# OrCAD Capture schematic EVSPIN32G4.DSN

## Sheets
1 PAGE1 - STSPIN32G4: size A4; rev: 1
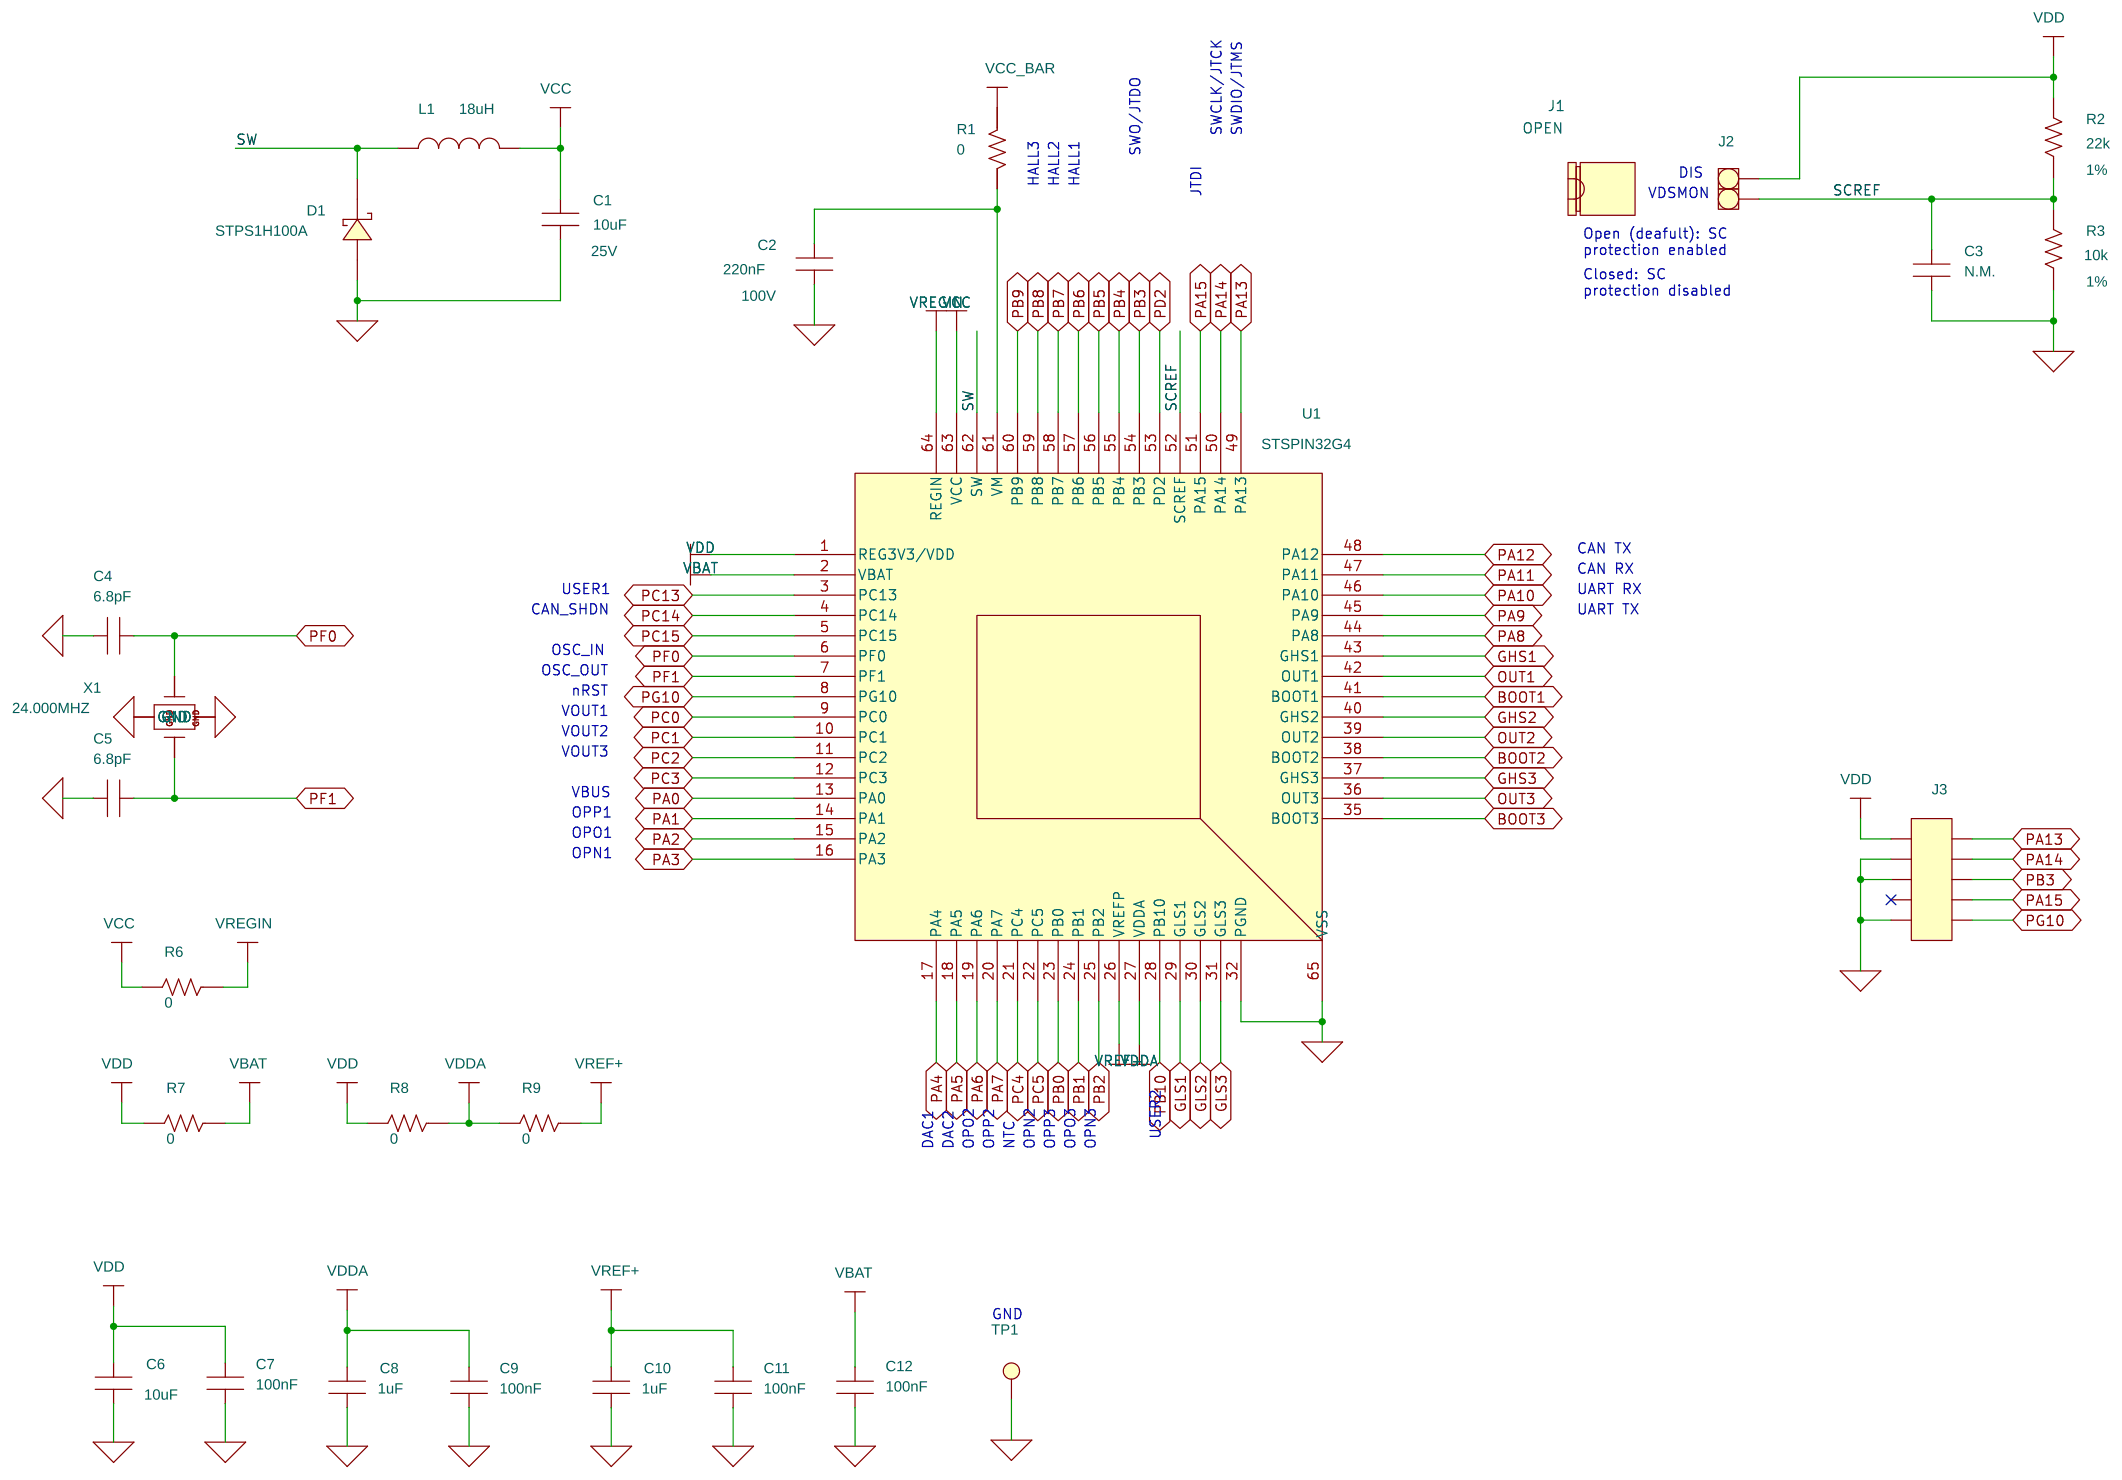
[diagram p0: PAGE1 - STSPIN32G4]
2 PAGE2 - Power Stage: size A4
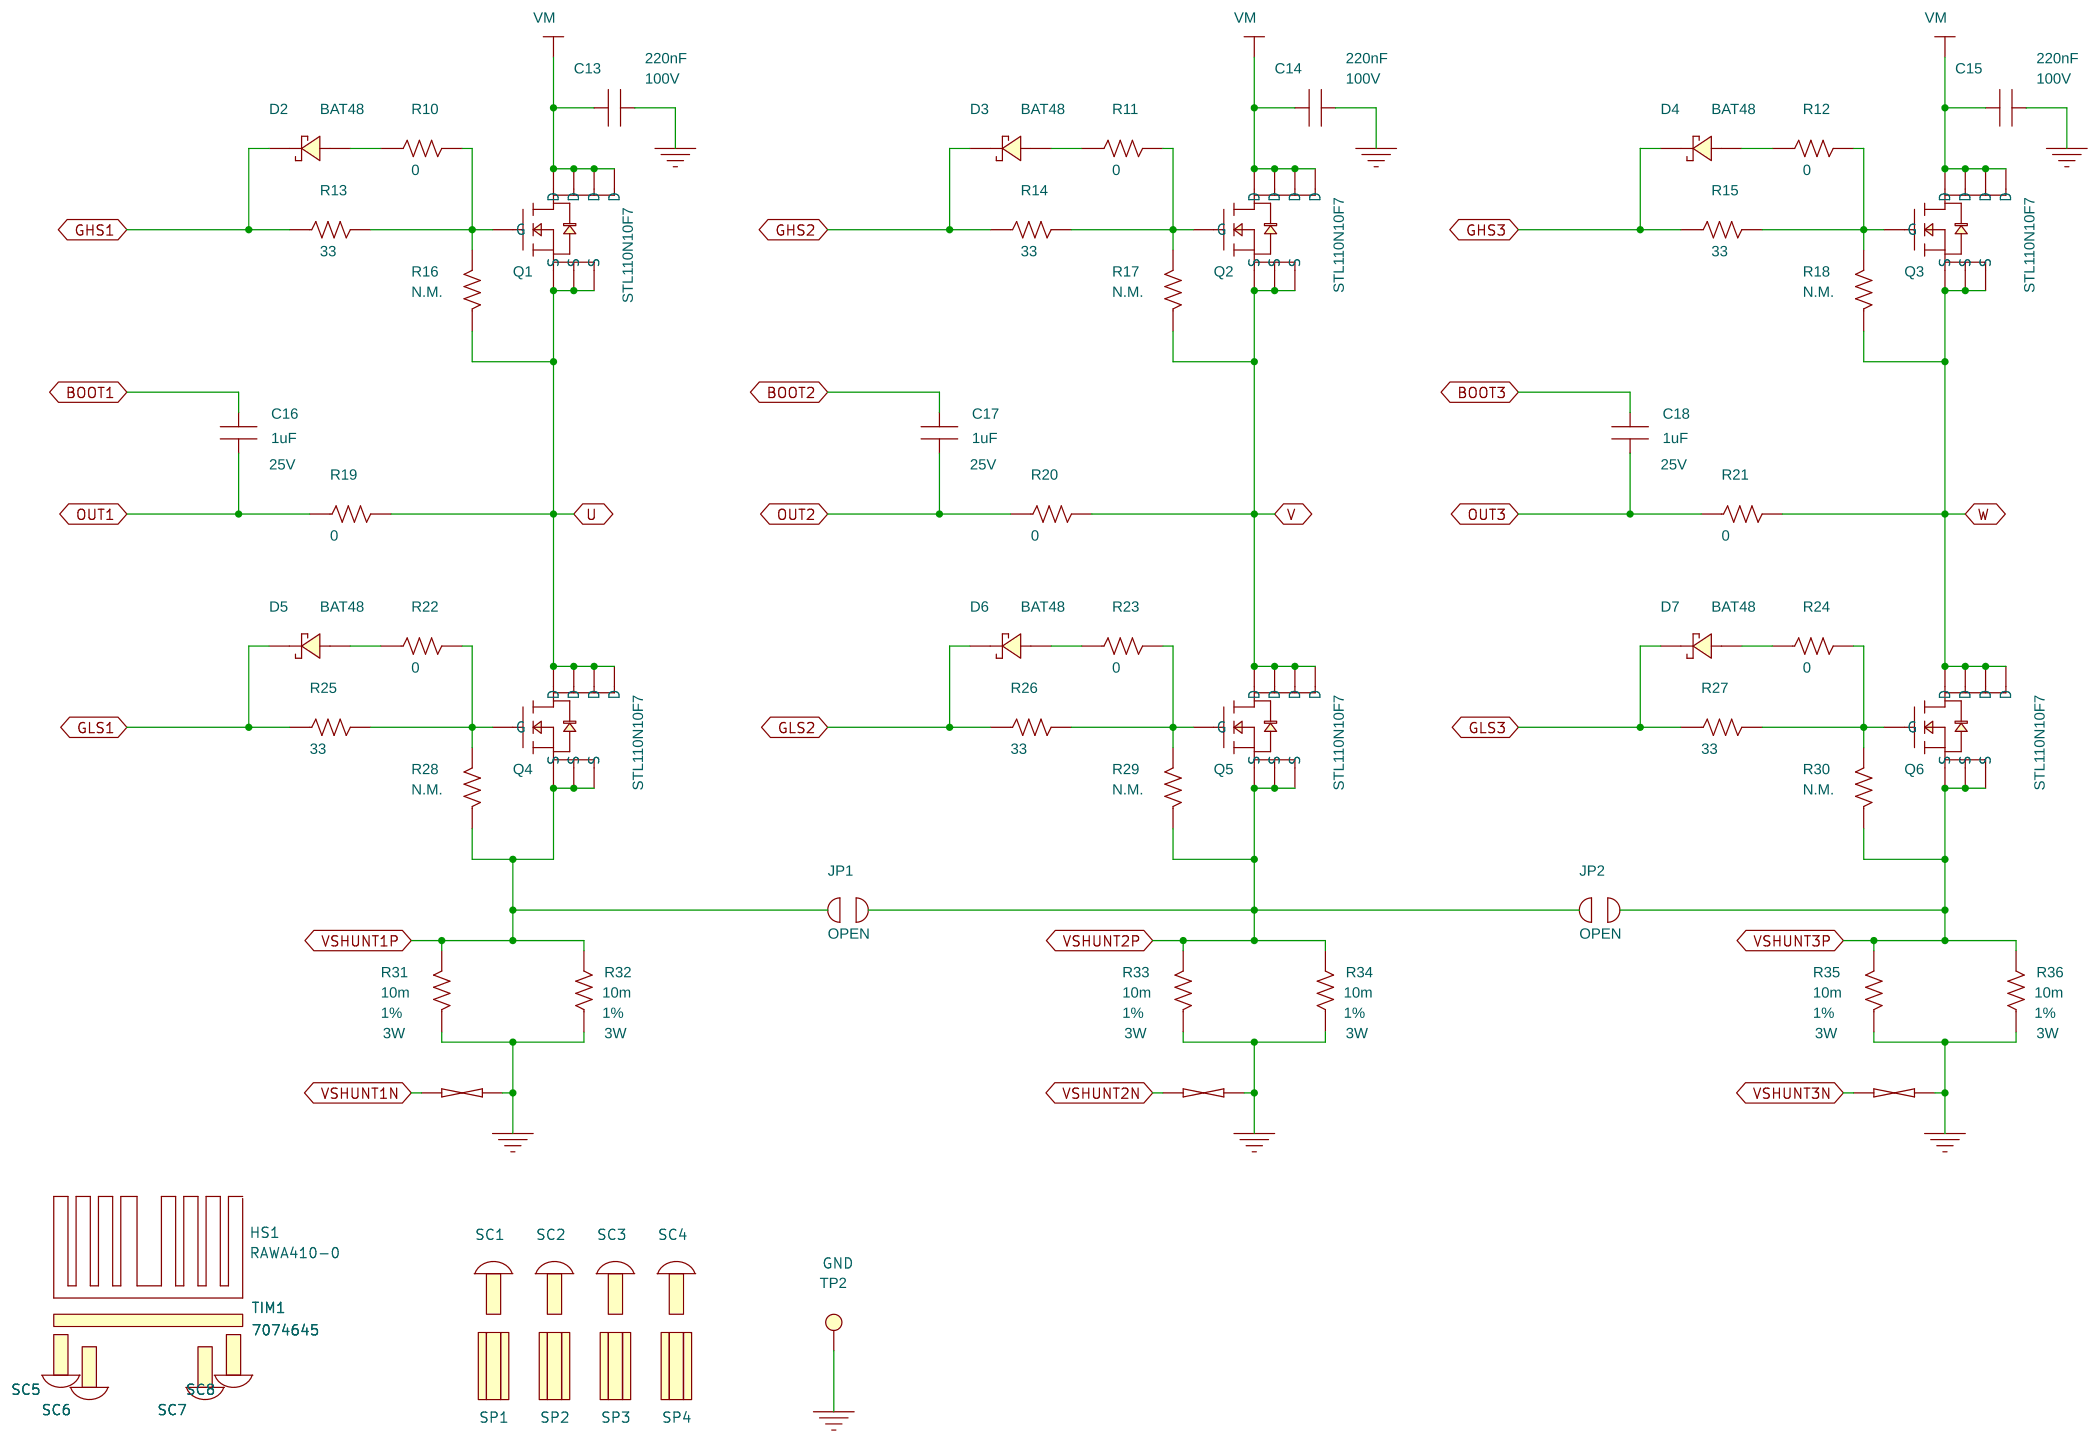
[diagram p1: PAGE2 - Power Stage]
3 PAGE3 - Analog Sensing: size A4
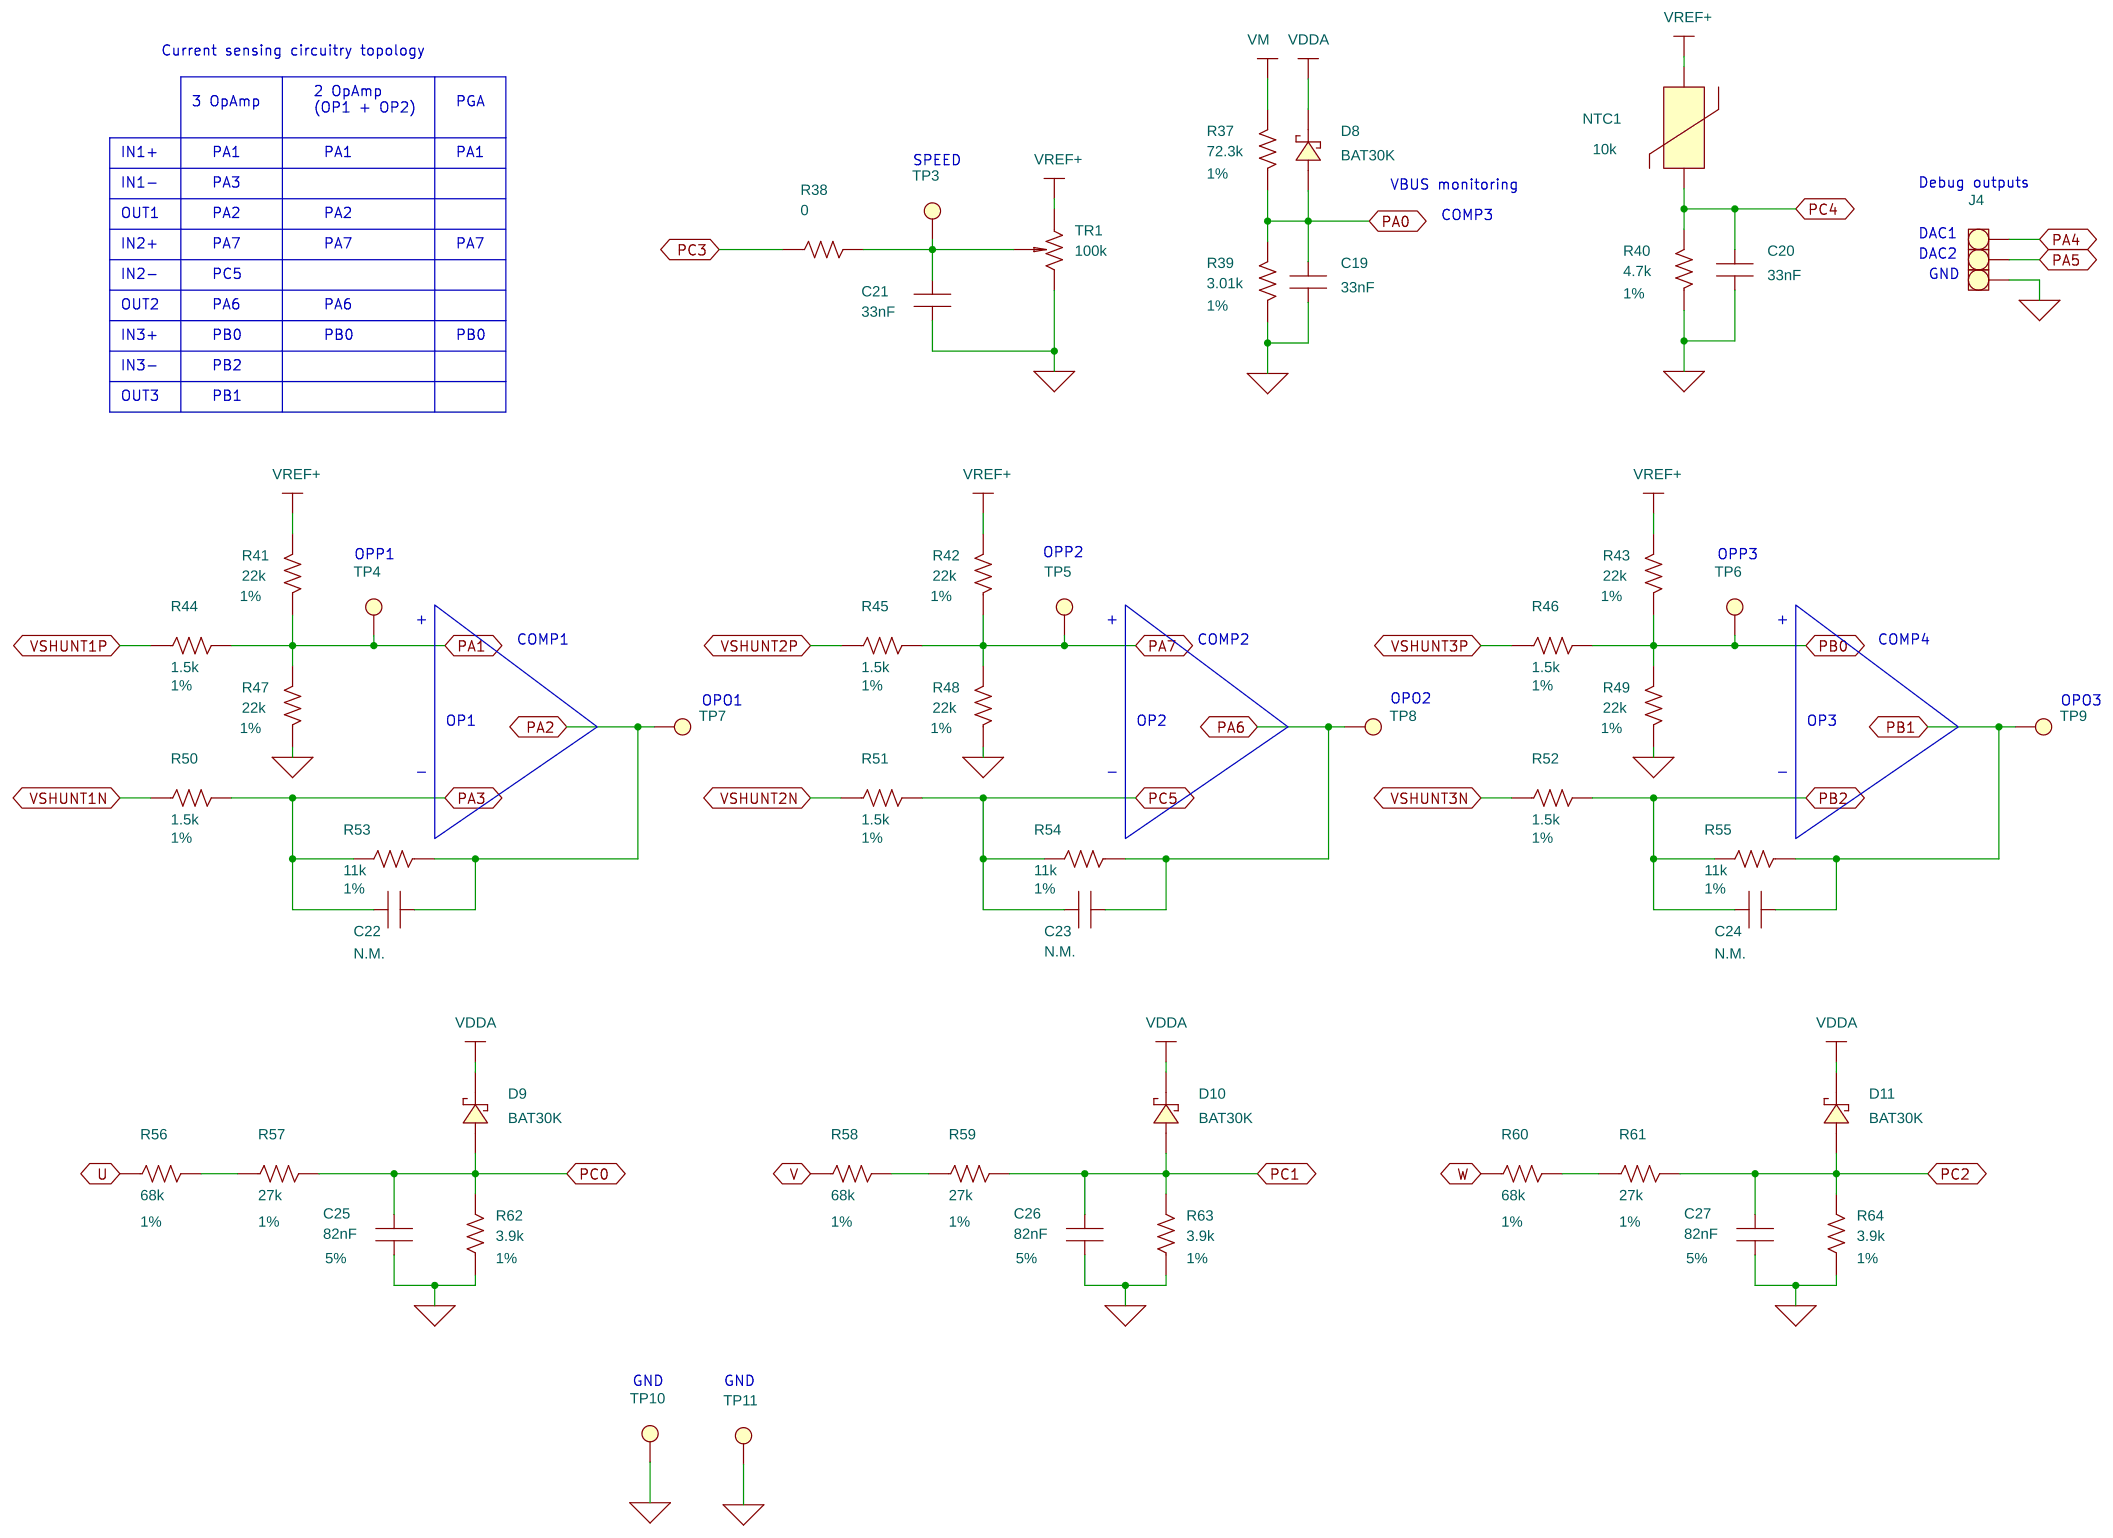
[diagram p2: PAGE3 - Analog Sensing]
4 PAGE4 - Arduino connector: size A4
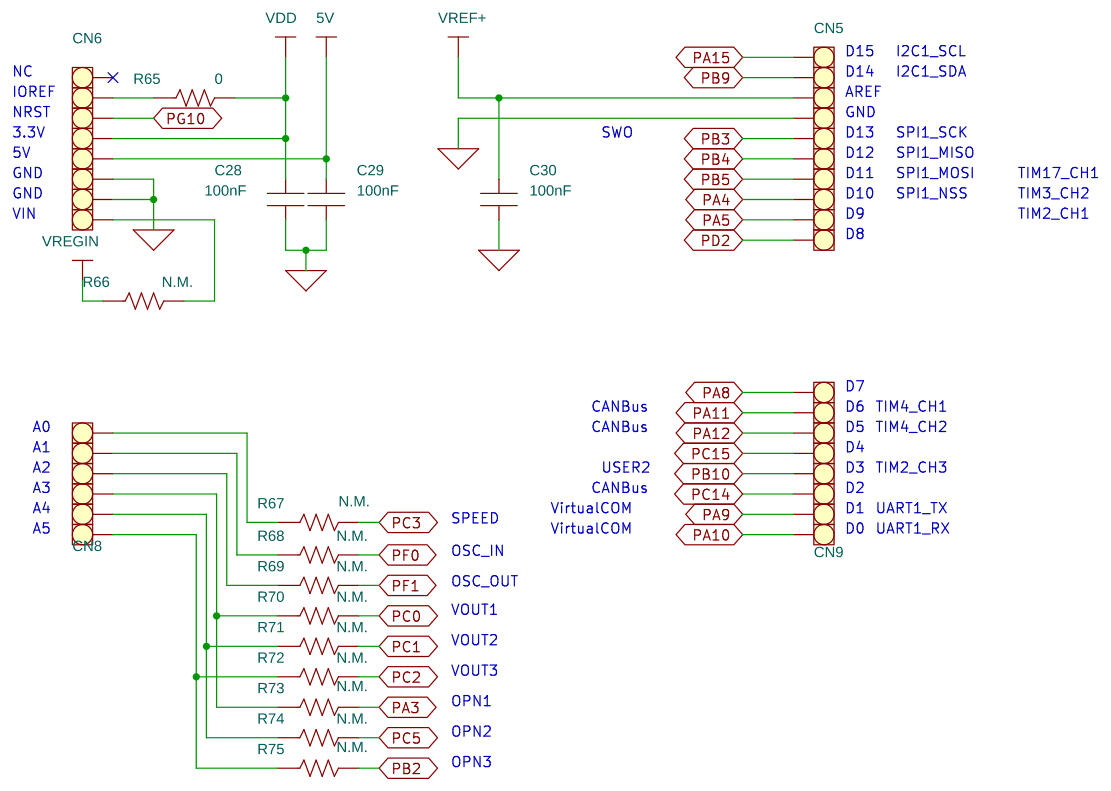
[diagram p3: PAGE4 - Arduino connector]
5 PAGE5 - Inputs and Outputs: size A4
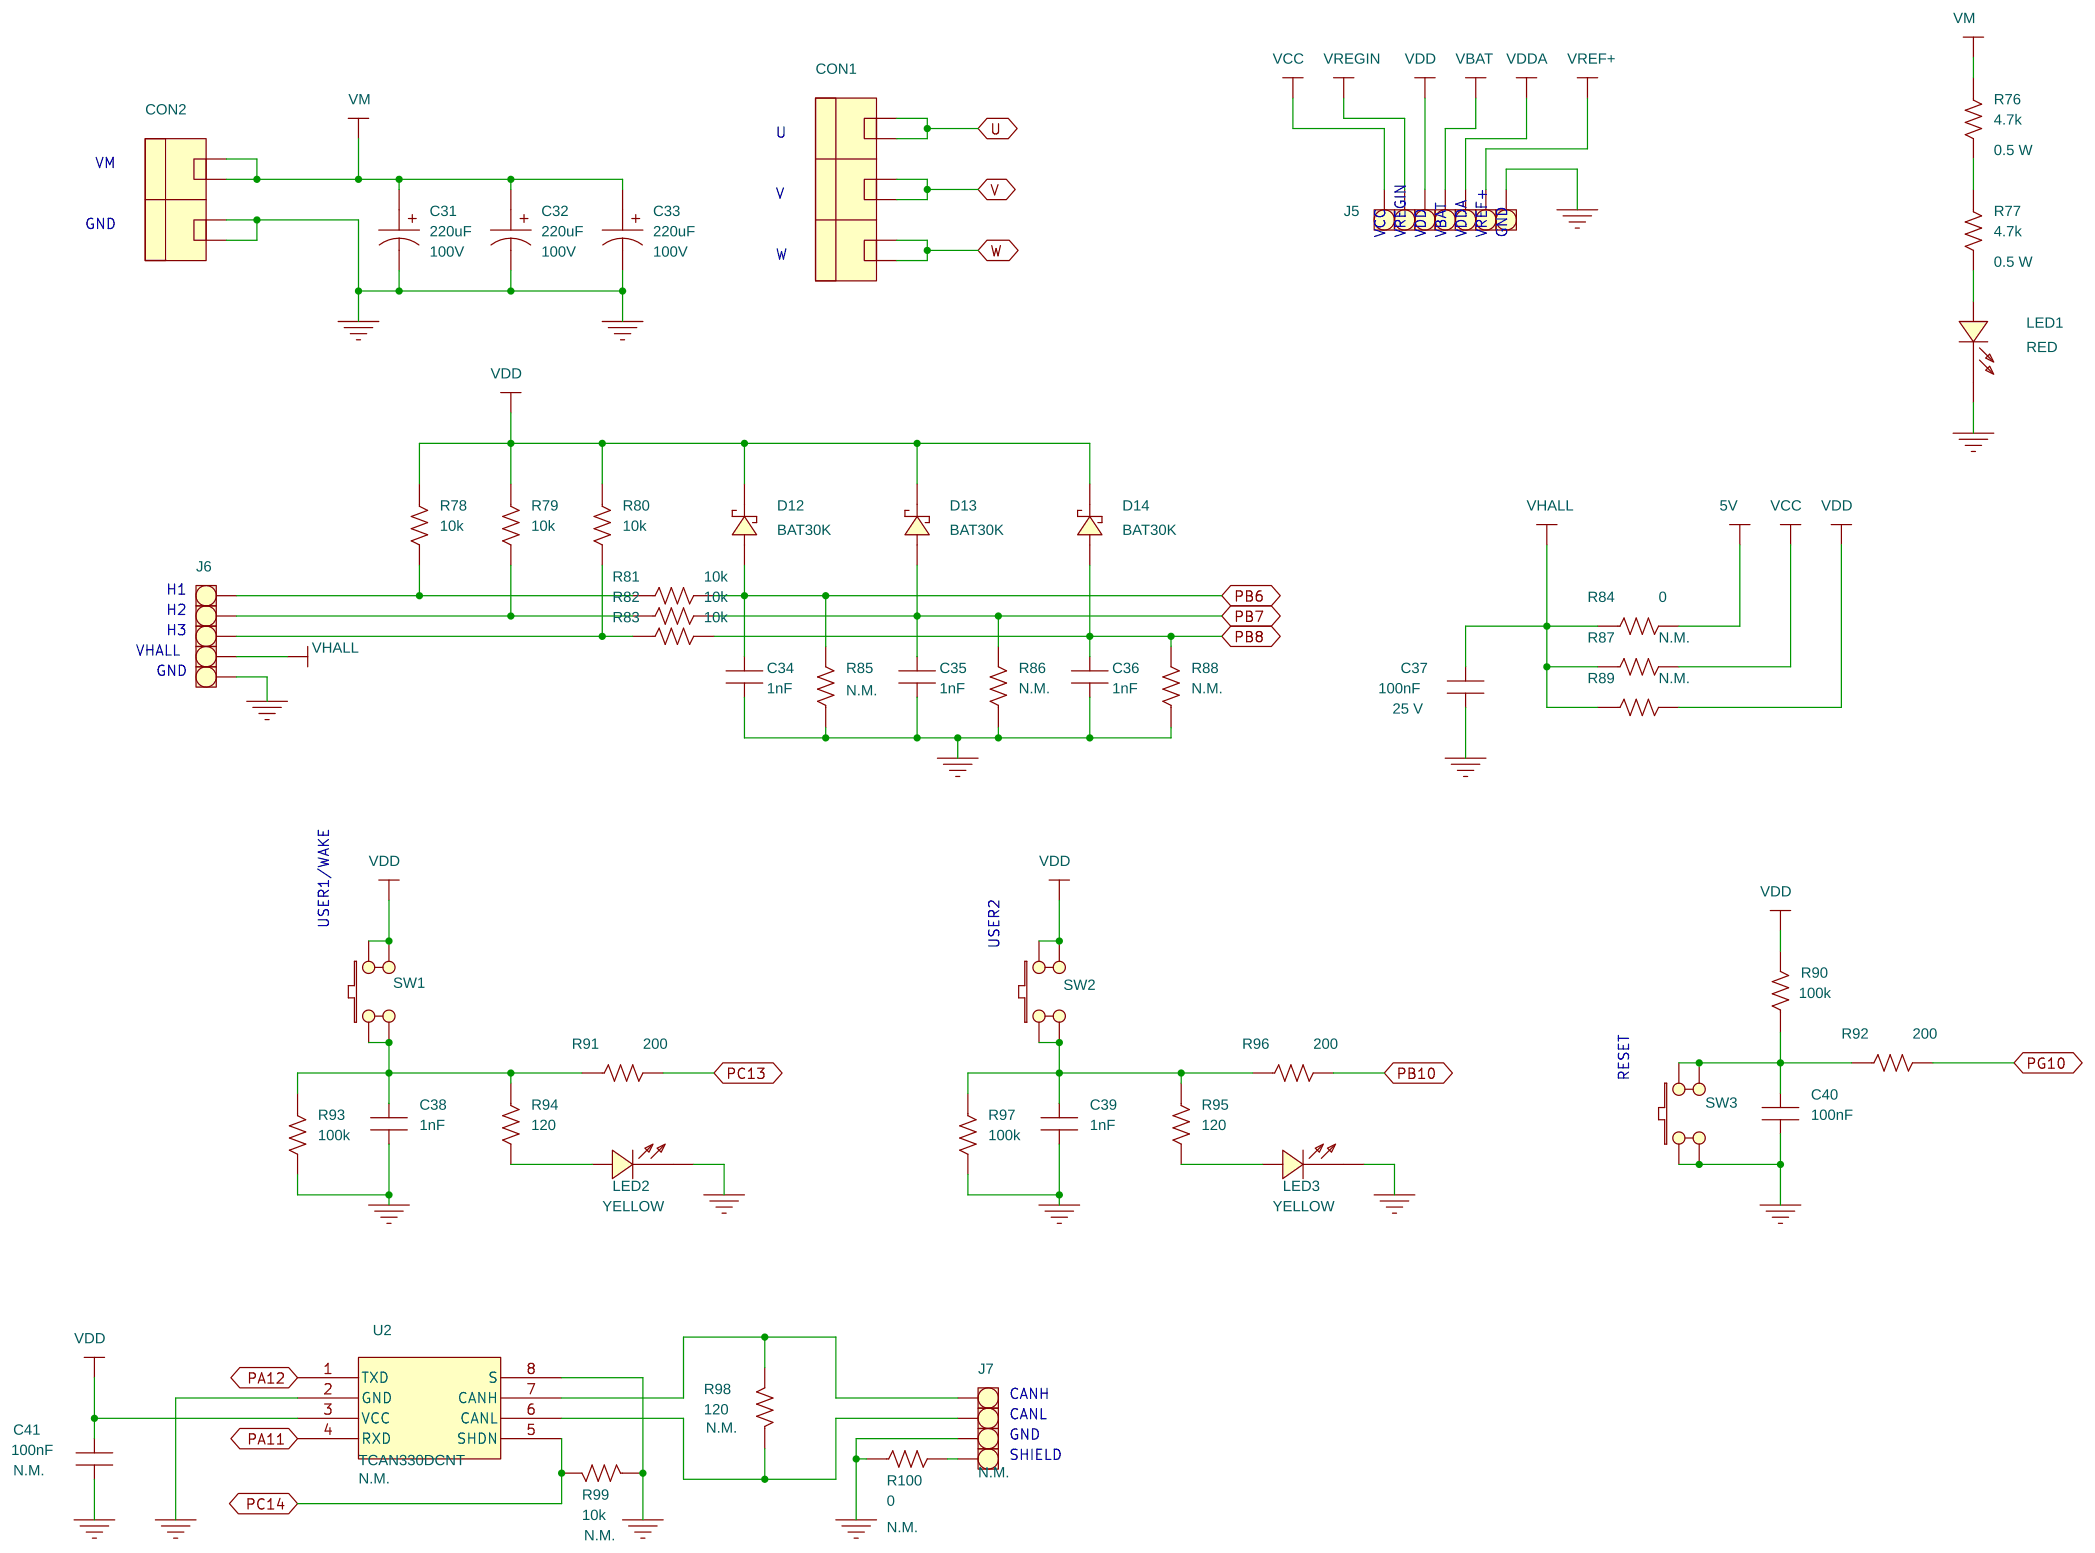
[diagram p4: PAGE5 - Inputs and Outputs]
6 PAGE6 - STLINK: size A4
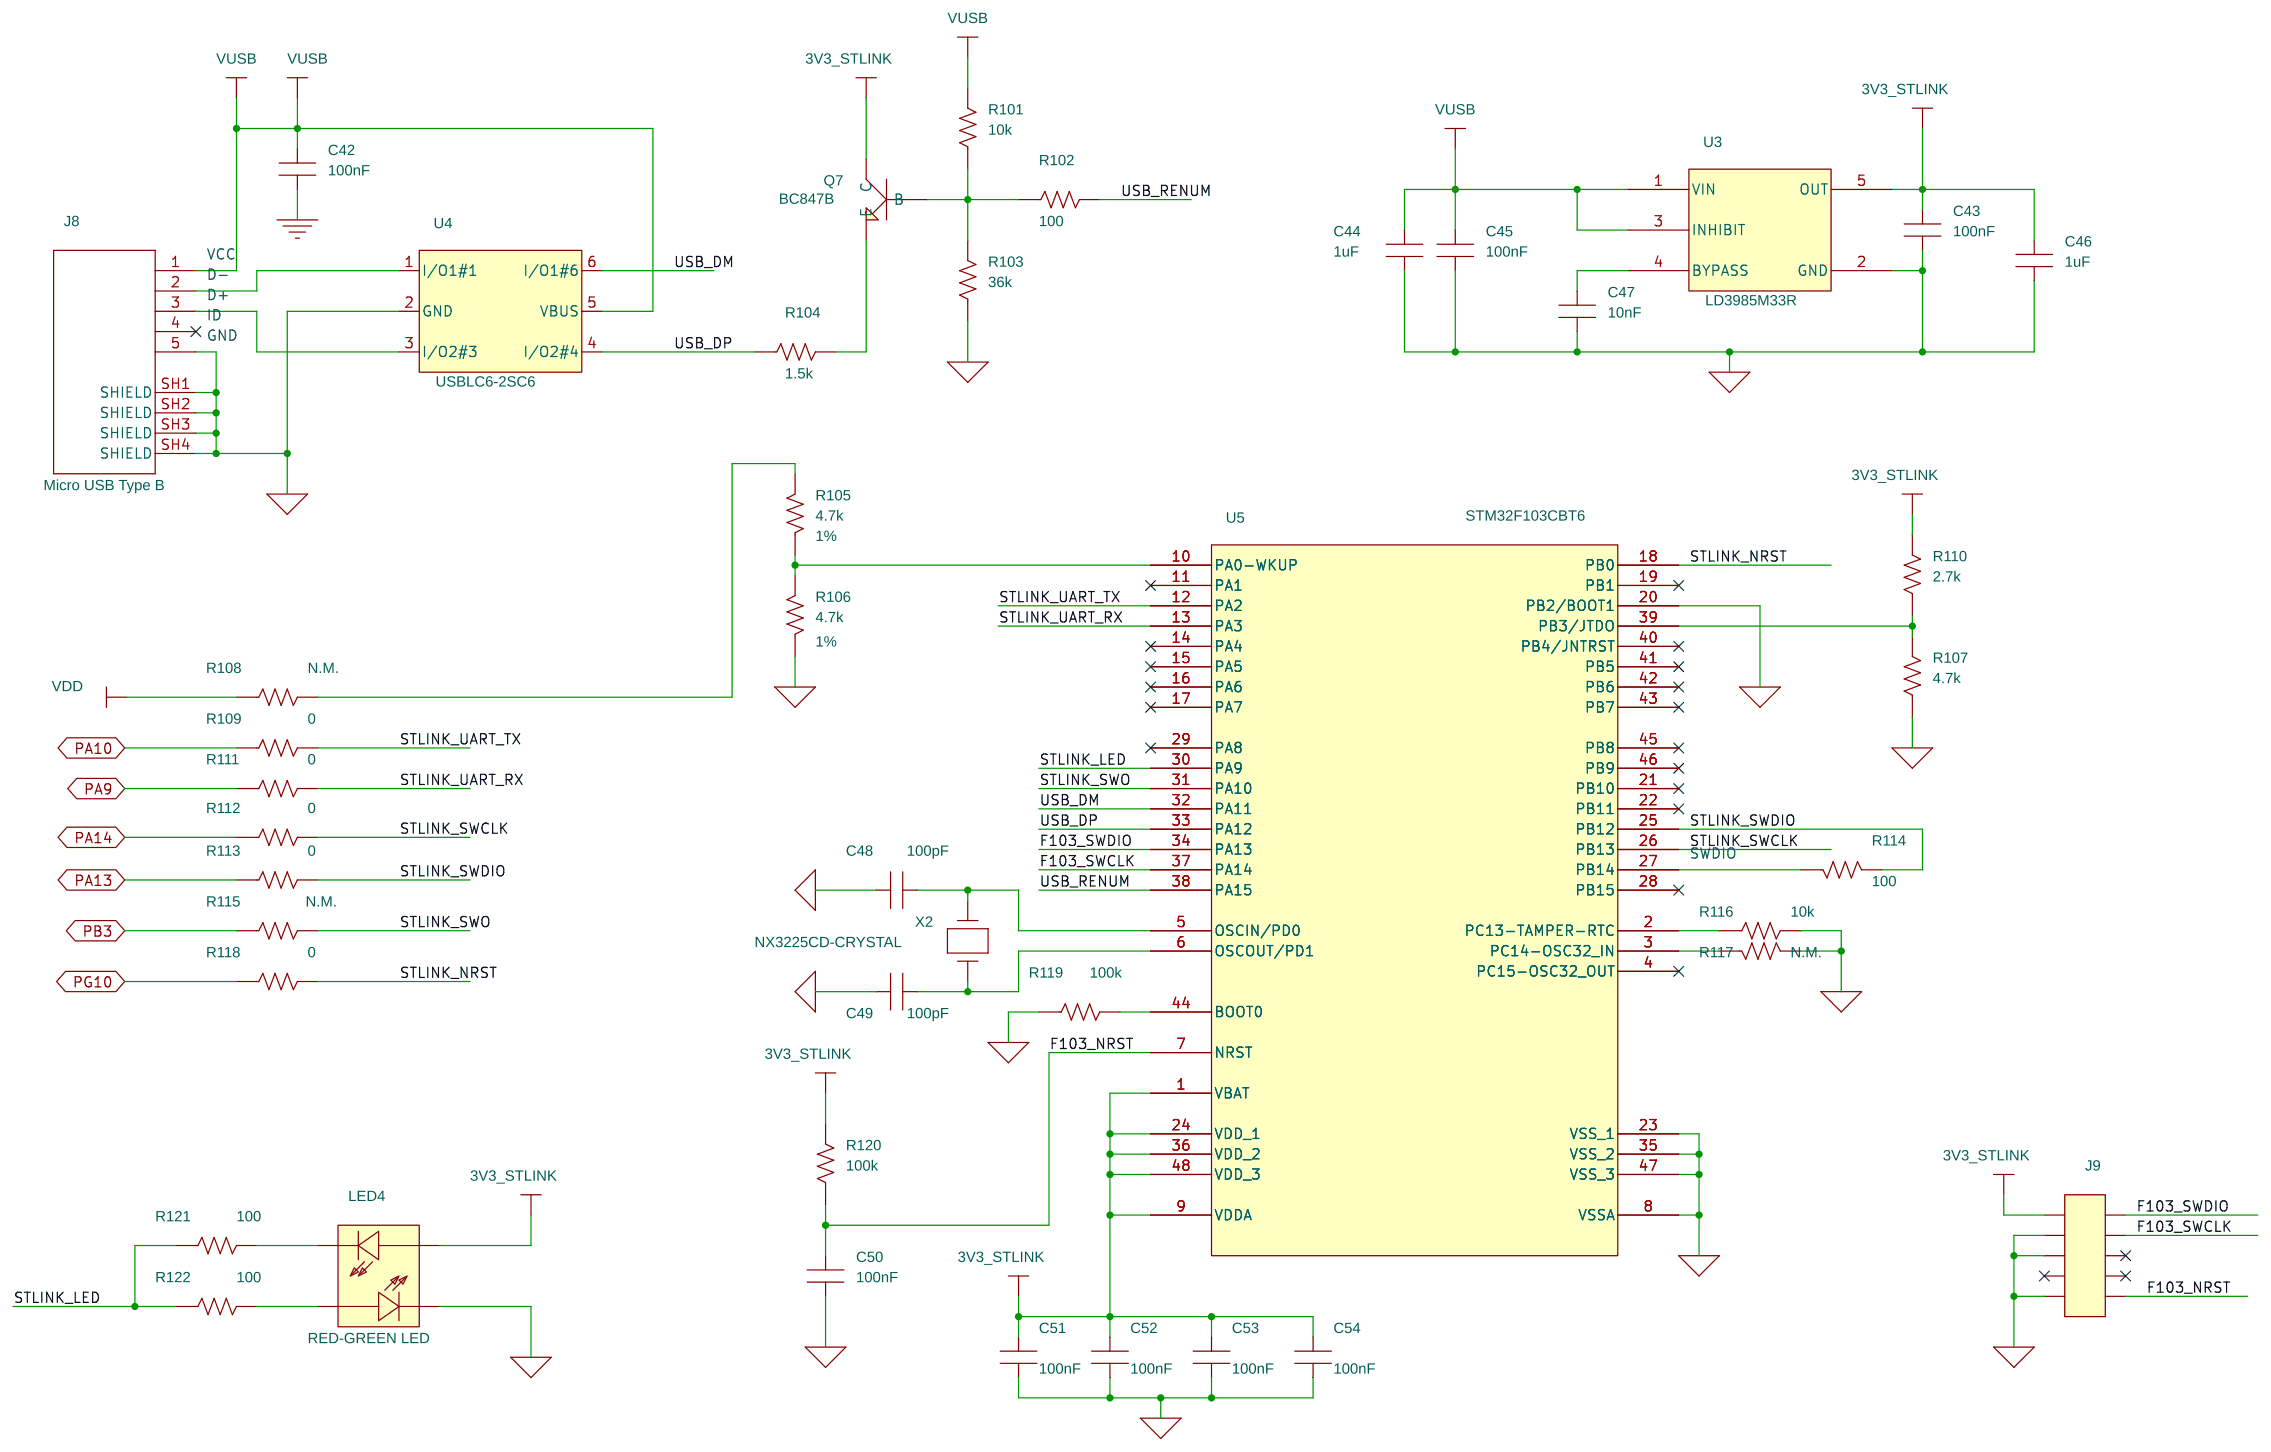
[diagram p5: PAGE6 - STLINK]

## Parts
sheet PAGE1 - STSPIN32G4
C1  10uF  [C0805]
C2  220nF  [C0805]
C3  C-0603  [C0603]
C4  6.8pF  [C0402]
C5  6.8pF  [C0402]
C6  10uF  [C0805]
C7  100nF  [C0603]
C8  1uF  [C0603]
C9  100nF  [C0603]
C10  1uF  [C0603]
C11  100nF  [C0603]
C12  100nF  [C0603]
D1  STPS1H100A  [SMA]
J1  OPEN
J2  STRIP 1x2  [STRIP254P-M-2]
J3  STRIP 2x5  [PIN2X5P127]
L1  18uH  [7447732115-WURTH]
R1  0  [J0805]
R2  22k  [R0603]
R3  10k  [R0603]
R6  0  [J0805]
R7  0  [J0805]
R8  0  [J0805]
R9  0  [J0805]
TP1  TP-SMD-S1751-46R  [tp_SMD_135_70]
U1  STSPIN32G4  [VFQFPN9x9x1_0-64L-EXP]
X1  24.000MHZ  [ABMM11W]
sheet PAGE2 - Power Stage
C13  220nF  [C0805]
C14  220nF  [C0805]
C15  220nF  [C0805]
C16  1uF  [C0805]
C17  1uF  [C0805]
C18  1uF  [C0805]
D2  BAT48  [SOD-323]
D3  BAT48  [SOD-323]
D4  BAT48  [SOD-323]
D5  BAT48  [SOD-323]
D6  BAT48  [SOD-323]
D7  BAT48  [SOD-323]
HS1  RAWA410-0
JP1  OPEN  [JUMPER-LARGO5_5MM]
JP2  OPEN  [JUMPER-LARGO5_5MM]
NET1  PCB short  [CurrentSense]
NET2  PCB short  [CurrentSense]
NET3  PCB short  [CurrentSense]
Q1  STL110N10F7  [PFLAT_6X5-8LEADS]
Q2  STL110N10F7  [PFLAT_6X5-8LEADS]
Q3  STL110N10F7  [PFLAT_6X5-8LEADS]
Q4  STL110N10F7  [PFLAT_6X5-8LEADS]
Q5  STL110N10F7  [PFLAT_6X5-8LEADS]
Q6  STL110N10F7  [PFLAT_6X5-8LEADS]
R10  0  [R0603]
R11  0  [R0603]
R12  0  [R0603]
R13  33  [R0603]
R14  33  [R0603]
R15  33  [R0603]
R16  R-0805  [R0603]
R17  R-0805  [R0603]
R18  R-0805  [R0603]
R19  0  [R0603]
R20  0  [R0603]
R21  0  [R0603]
R22  0  [R0603]
R23  0  [R0603]
R24  0  [R0603]
R25  33  [R0603]
R26  33  [R0603]
R27  33  [R0603]
R28  R-0805  [R0603]
R29  R-0805  [R0603]
R30  R-0805  [R0603]
R31  10m  [R2512]
R32  10m  [R2512]
R33  10m  [R2512]
R34  10m  [R2512]
R35  10m  [R2512]
R36  10m  [R2512]
SC1  M3
SC2  M3
SC3  M3
SC4  M3
SC5  M3
SC6  M3
SC7  M3
SC8  M3
SP1  222424
SP2  222424
SP3  222424
SP4  222424
TIM1  7074645
TP2  TP-SMD-S1751-46R  [tp_SMD_135_70]
sheet PAGE3 - Analog Sensing
C19  33nF  [C0603]
C20  33nF  [C0603]
C21  33nF  [C0603]
C22  C-0603  [C0603]
C23  C-0603  [C0603]
C24  C-0603  [C0603]
C25  82nF  [C0603]
C26  82nF  [C0603]
C27  82nF  [C0603]
D8  BAT30K  [SOD523]
D9  BAT30K  [SOD523]
D10  BAT30K  [SOD523]
D11  BAT30K  [SOD523]
J4  STRIP 1x3  [STRIP254P-M-3]
NTC1  10k  [R0603]
R37  72.3k  [R0603]
R38  0  [J0805]
R39  3.01k  [R0603]
R40  4.7k  [R0603]
R41  22k  [R0603]
R42  22k  [R0603]
R43  22k  [R0603]
R44  1.5k  [R0603]
R45  1.5k  [R0603]
R46  1.5k  [R0603]
R47  22k  [R0603]
R48  22k  [R0603]
R49  22k  [R0603]
R50  1.5k  [R0603]
R51  1.5k  [R0603]
R52  1.5k  [R0603]
R53  11k  [R0603]
R54  11k  [R0603]
R55  11k  [R0603]
R56  68k  [R0603]
R57  27k  [R0603]
R58  68k  [R0603]
R59  27k  [R0603]
R60  68k  [R0603]
R61  27k  [R0603]
R62  3.9k  [R0603]
R63  3.9k  [R0603]
R64  3.9k  [R0603]
TP3  TP-SMD-diam1_5mm  [TP-D60]
TP4  TP-SMD-diam1_5mm  [TP-D60]
TP5  TP-SMD-diam1_5mm  [TP-D60]
TP6  TP-SMD-diam1_5mm  [TP-D60]
TP7  TP-SMD-diam1_5mm  [TP-D60]
TP8  TP-SMD-diam1_5mm  [TP-D60]
TP9  TP-SMD-diam1_5mm  [TP-D60]
TP10  TP-diam1_27mm-Hole0_8mm  [TP-SONDA]
TP11  TP-diam1_27mm-Hole0_8mm  [TP-SONDA]
TR1  100k  [TRIMMER-3386P-BOURNS]
sheet PAGE4 - Arduino connector
C28  100nF  [C0603]
C29  100nF  [C0603]
C30  100nF  [C0603]
CN5  STRIP-P2_54-10P-FEMALE  [SIL-SOCKET10PIN-P254]
CN6  STRIP-P2_54-8P-FEMALE  [SIL-SOCKET8PIN-P254]
CN8  STRIP-P2_54-6P-FEMALE  [SIL-SOCKET6PIN-P254]
CN9  STRIP-P2_54-8P-FEMALE  [SIL-SOCKET8PIN-P254]
R65  0  [J0805]
R66  0  [J0805]
R67  0  [J0805]
R68  0  [J0805]
R69  0  [J0805]
R70  0  [J0805]
R71  0  [J0805]
R72  0  [J0805]
R73  0  [J0805]
R74  0  [J0805]
R75  0  [J0805]
sheet PAGE5 - Inputs and Outputs
C31  220uF  [D500p200]
C32  220uF  [D500p200]
C33  220uF  [D500p200]
C34  1nF  [C0603]
C35  1nF  [C0603]
C36  1nF  [C0603]
C37  100nF  [C0603]
C38  1nF  [C0603]
C39  1nF  [C0603]
C40  100nF  [C0603]
C41  100nF  [C0603]
CON1  Power con3P  [2834082-2-TE]
CON2  Power con2P  [2834082-1-TE]
D12  BAT30K  [SOD523]
D13  BAT30K  [SOD523]
D14  BAT30K  [SOD523]
J5  STRIP 1x7  [STRIP254P-M-7]
J6  STRIP 1x5  [STRIP254P-M-5]
J7  STRIP 1x4  [STRIP254P-M-4]
LED1  RED  [led-0805]
LED2  YELLOW  [led-0603]
LED3  YELLOW  [led-0603]
R76  4.7k  [R0805]
R77  4.7k  [R0805]
R78  10k  [R0603]
R79  10k  [R0603]
R80  10k  [R0603]
R81  10k  [R0603]
R82  10k  [R0603]
R83  10k  [R0603]
R84  0  [J0805]
R85  R-0603  [R0603]
R86  R-0603  [R0603]
R87  0  [J0805]
R88  R-0603  [R0603]
R89  0  [J0805]
R90  100k  [R0603]
R91  200  [R0603]
R92  200  [R0603]
R93  100k  [R0603]
R94  120  [R0603]
R95  120  [R0603]
R96  200  [R0603]
R97  100k  [R0603]
R98  120  [R0603]
R99  10k  [R0603]
R100  0  [J0805]
SW1  6x6 J-bend SMT  [BUTTON_L6_2_W6_2]
SW2  6x6 J-bend SMT  [BUTTON_L6_2_W6_2]
SW3  6x6 J-bend SMT  [BUTTON_L6_2_W6_2]
U2  TCAN330DCNT  [SOT23-8L]
sheet PAGE6 - STLINK
C42  100nF  [C0603]
C43  100nF  [C0603]
C44  1uF  [C0603]
C45  100nF  [C0603]
C46  1uF  [C0603]
C47  10nF  [C0603]
C48  100pF  [C0603]
C49  100pF  [C0603]
C50  100nF  [C0603]
C51  100nF  [C0603]
C52  100nF  [C0603]
C53  100nF  [C0603]
C54  100nF  [C0603]
J8  Micro USB Type B  [629105150521-USB-MICRO-B-WE]
J9  STRIP 2x5  [PIN2X5P127]
LED4  RED-GREEN LED  [PLCC4]
Q7  BC847B  [SOT23]
R101  10k  [R0603]
R102  100  [R0603]
R103  36k  [R0603]
R104  1.5k  [R0603]
R105  4.7k  [R0603]
R106  4.7k  [R0603]
R107  4.7k  [R0603]
R108  0  [J0805]
R109  0  [J0805]
R110  2.7k  [R0603]
R111  0  [J0805]
R112  0  [J0805]
R113  0  [J0805]
R114  100  [R0603]
R115  0  [J0805]
R116  10k  [R0603]
R117  R-0603  [R0603]
R118  0  [J0805]
R119  100k  [R0603]
R120  100k  [R0603]
R121  100  [R0603]
R122  100  [R0603]
U3  LD3985M33R  [SOT23-5L]
U4  USBLC6-2SC6  [SOT23-6L]
U5  STM32F103CBT6  [LQFP48_L7_W7_P0_5]
X2  NX3225CD-CRYSTAL  [XTAL_L3_2_W2_5_2PINS]

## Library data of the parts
C1 = C-0805: TOLERANCE: 10%; VOLTAGE: 25V
C2 C13-C15 = C-0805: TOLERANCE: 10%; VOLTAGE: 100V
C3 C22-C24 C41 = C-0603: Mounting: N.M.; TOLERANCE: 10%; VOLTAGE: 6.3V
C4 C5 = C-0402: TOLERANCE: 0.25pF; VOLTAGE: 6.3V
C6 = C-0805: TOLERANCE: 10%; VOLTAGE: 6.3V
C7 C9 C11 C12 C19-C21 C28-C30 C34-C36 C38-C40 C42 C43 C45 C47-C54 = C-0603: TOLERANCE: 10%; VOLTAGE: 6.3V
C8 C10 C44 C46 = C-0603: Manufacturer: WURTH ELEKTRONIK; Part Number: 885012206076; TOLERANCE: 10%; VOLTAGE: 6.3V
D1 = STPS1H100A: Voltage: 100V
J1 = Jumper: Manufacturer: WURTH ELEKTRONIK; Package: 2.54mm; Part Number: 60900213421 or equivalent
J2 = STRIP_1x2
J3 J9 = STRIP_2x5: Manufacturer: WURTH ELEKTRONIK; Part Number: 62201021121 or FTSH-105-01-F-D-K
L1 = INDUCTOR-7447732115-WE: ISAT: 1A; Manufacturer: WURTH ELEKTRONIK; Part Number: 744045180 or 7447732115
R1 R6-R9 R38 R65 R84 R109 R111-R113 R118 = R-0603: POWER: 0.1W; Package: Size 0805; TOLERANCE: 5%
R2 R3 R37 R39-R64 R105 R106 = R-0603: POWER: 0.1W; TOLERANCE: 1%
TP1 TP2 = TP-SMD-S2761-46R: Part Number: S1751-46R or equivalent
U1 = STSPIN32G4
X1 = CRYSTAL-ABM11W
C16-C18 = C-0805: Manufacturer: WURTH ELEKTRONIK; Part Number: 885012207078; TOLERANCE: 10%; VOLTAGE: 25V
D2-D7 = BAT60J: Part Number: BAT48JFILM or equivalent; VOLTAGE: 40 V
HS1 = HS-501: Heatsink; Manufacturer: SCHAFFNER; Package: 47.5mm x 51.3mm; Part Number: RAWA410-0 or Equivalent
JP1 JP2 = Jumper_a_Goccia-Largo_5_5mm: Mounting: N.M.
NET1-NET3 = CurrentSense: Mounting: N.M.
Q1-Q6 = STLD110N10F7: N-channel 100 V, 5 mO typ., 107 A STripFET F7 Power MOSFET; Package: PowerFLAT 5x6; Part Number: STL110N10F7 or equivalent
R10-R15 R19-R27 = R-0805: POWER: 0.1W; Package: Size 0603; TOLERANCE: 5%
R16-R18 R28-R30 = R-0805: Mounting: N.M.; POWER: 0.1W; Package: Size 0603; TOLERANCE: 5%
R31-R36 = R-2512: Manufacturer: Bourns; POWER: 3W; Part Number: CRA2512-FZ-R010ELF or equivalent; TOLERANCE: 1%
SC1-SC8 = M3: M3 Cheese-head screw; Package: M3x8mm
SP1-SP4 = 222424: M3 F-F Hexagonal spacer 20 mm; Manufacturer: RS-PRO; Part Number: 222-424
TIM1 = 7074645: Thermally conductive Gap filler, 150x150 mm sp.0,5 mm.; Manufacturer: RS-PRO; Package: 47.5mm x 51.3mm; Part Number: 707-4645
C25-C27 = C-0603: TOLERANCE: 5%; VOLTAGE: 6.3V
D8-D14 = BAT30K
J4 = STRIP_1x3: Manufacturer: WURTH ELEKTRONIK; Part Number: 61300311121 or equivalent
NTC1 = NTC-NCP18XH103F03RB: TOLERANCE: 1%
TP3-TP9 = TP-SMD-diam1_5mm: Mounting: N.M.
TP10 TP11 = TP-diam1_27mm-Hole0_8mm: Mounting: N.M.
TR1 = TRIMMER_3386P: Part Number: 3386P-1-104 T x LF or equivalent
CN5 = STRIP-P2_54-10P-FEMALE: Manufacturer: WURTH ELEKTRONIK; Part Number: 61301011821 or SSQ-110-21-F-S
CN6 CN9 = STRIP-P2_54-8P-FEMALE: Manufacturer: WURTH ELEKTRONIK; Part Number: 61300811821 or SSQ-108-21-F-S
CN8 = STRIP-P2_54-6P-FEMALE: Manufacturer: WURTH ELEKTRONIK; Part Number: 61300611821 or SSQ-106-21-F-S
R66-R75 R87 R89 R100 R108 R115 = R-0603: Mounting: N.M.; POWER: 0.1W; Package: Size 0805; TOLERANCE: 5%
C31-C33 = CAP_POL: THT Electrolytic Capacitor; Manufacturer: WURTH ELEKTRONIK; Package: TH diam12.5-h35mm; Part Number: 860040878017 or EEUFC2A221L; TOLERANCE: 20%; Voltage: 100V
C37 = C-0603: TOLERANCE: 10%; VOLTAGE: 25 V
CON1 = TE_con3P_20A_p5mm: 5.0 mm Horizontal Entry Screwless Connector; Manufacturer: TE Connectivity; Package: 3 poles, pitch 5.0 mm; Part Number: 2834082-2 or equivalent
CON2 = TE_con2P_20A_p5mm: 5.0 mm Horizontal Entry Screwless Connector; Manufacturer: TE Connectivity; Package: 2 poles, pitch 5.0 mm; Part Number: 2834082-1 or equivalent
J5 = STRIP_1x7: Part Number: 61300311121 or equivalent
J6 = STRIP_1x5
J7 = STRIP_1x4: Mounting: N.M.
LED1 = LED-0805-RED-WE
LED2 LED3 = LED-0603-YELLOW-WE
R76 R77 = R-0603: POWER: 0.5 W; Package: Size 0805; TOLERANCE: 5%
R78-R83 R90 R93-R95 R97 R101-R104 R107 R110 R114 R116 R119-R122 = R-0603: POWER: 0.1W; TOLERANCE: 5%
R85 R86 R88 R98 R99 R117 = R-0603: Mounting: N.M.; POWER: 0.1W; TOLERANCE: 5%
R91 R92 R96 = R-0603: POWER: 0.1W; Package: Size 0603; TOLERANCE: 5%
SW1-SW3 = 430483025816
U2 = TCAN330DCNT: Manufacturer: TEXAS INSTRUMENTS; Mounting: N.M.; Package: SOT-23 8L; Part Number: (TCAN330DCNT or Equivalent)
J8 = USB-microB-629105150521-WE-SMT
LED4 = HSMF-A201-A00J1
Q7 = BC847B
U3 = LD3985M33R: Part Number: LD3985M33R or Equivalent
U4 = USBLC6-2SC6: Part Number: USBLC6-2SC6 / YCRA2512-FZ-R050ELF or equivalent
U5 = STM32F103CBT6
X2 = NX3225CD-CRYSTAL

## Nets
3V3_STLINK: C43.2 C46.2 C51.2 C52.2 C53.2 C54.2 J9.1 LED4.A2 Q7.3(C) R110.2 R120.2 U3.5(OUT) U5.1(VBAT) U5.9(VDDA) U5.24(VDD_1) U5.36(VDD_2) U5.48(VDD_3)
5V: C29.1 C42.2 C44.2 C45.2 CN6.5 J8.1 R84.2 R101.2 U3.1(VIN) U3.3(INHIBIT) U4.5(VBUS)
GND: C1.1 C2.1 C3.1 C4.2 C5.1 C6.1 C7.2 C8.1 C9.2 C10.1 C11.2 C12.2 C13.1 C14.1 C15.1 C19.1 C20.1 C21.1 C25.1 C26.1 C27.1 C28.2 C29.2 C30.2 C31.2 C32.2 C33.2 C34.2 C35.2 C36.2 C37.1 C38.2 C39.2 C40.2 C41.2 C42.1 C43.1 C44.1 C45.1 C46.1 C47.1 C48.2 C49.2 C50.1 C51.1 C52.1 C53.1 C54.1 CN5.7 CN6.6 CN6.7 CON2.3 CON2.4 D1.2 J3.3 J3.5 J3.9 J4.3 J5.7 J6.5 J7.3 J8.5 J8.SH1(SHIELD) J8.SH2(SHIELD) J8.SH3(SHIELD) J8.SH4(SHIELD) J9.3 J9.5 J9.9 LED1.1 LED2.1 LED3.1 LED4.K1 NET1.2 NET2.2 NET3.2 R3.1 R31.1 R32.1 R33.1 R34.1 R35.1 R36.1 R39.1 R40.1 R47.1 R48.1 R49.1 R62.1 R63.1 R64.1 R85.1 R86.1 R88.1 R93.2 R97.2 R99.1 R100.1 R103.1 R106.1 R107.1 R116.2 R117.2 R119.1 SW3.3 SW3.4 TP1.1 TP2.1 TP10.1 TP11.1 TR1.3 U1.32(PGND) U1.65(VSS) U2.2(GND) U2.8(S) U3.2(GND) U4.2(GND) U5.8(VSSA) U5.20(PB2/BOOT1) U5.23(VSS_1) U5.35(VSS_2) U5.47(VSS_3) X1.2(GND) X1.4(GND)
VBAT: C12.1 J5.4 R7.1 U1.2(VBAT)
VCC: C1.2 J5.1 L1.2 R6.2 R87.2 U1.63(VCC)
VDD: C6.2 C7.1 C28.1 C41.1 CN6.4 D12.1(C) D13.1(C) D14.1(C) J2.1 J3.1 J5.3 R2.2 R7.2 R8.2 R65.2 R78.1 R79.1 R80.1 R89.2 R90.2 R108.1 SW1.3 SW1.4 SW2.3 SW2.4 U1.1(REG3V3/VDD) U2.3(VCC)
VDDA: C8.2 C9.1 D8.1(C) D9.1(C) D10.1(C) D11.1(C) J5.5 R8.1 R9.2 U1.27(VDDA)
BOOT1: C16.2 U1.41(BOOT1)
BOOT2: C17.2 U1.38(BOOT2)
BOOT3: C18.2 U1.35(BOOT3)
F103_NRST: C50.2 J9.10 R120.1 U5.7(NRST)
F103_SWCLK: J9.4 U5.37(PA14)
F103_SWDIO: J9.2 U5.34(PA13)
GHS1: D2.1(C) R13.1 U1.43(GHS1)
GHS2: D3.1(C) R14.1 U1.40(GHS2)
GHS3: D4.1(C) R15.1 U1.37(GHS3)
GLS1: D5.1(C) R25.1 U1.29(GLS1)
GLS2: D6.1(C) R26.1 U1.30(GLS2)
GLS3: D7.1(C) R27.1 U1.31(GLS3)
OUT1: C16.1 R19.1 U1.42(OUT1)
OUT2: C17.1 R20.1 U1.39(OUT2)
OUT3: C18.1 R21.1 U1.36(OUT3)
PA0: C19.2 D8.2(A) R37.1 R39.2 U1.13(PA0)
PA1: R41.1 R44.2 R47.2 TP4.1 U1.14(PA1)
PA2: C22.2 R53.1 TP7.1 U1.15(PA2)
PA3: C22.1 R50.2 R53.2 R73.2 U1.16(PA3)
PA4: CN5.3 J4.1 U1.17(PA4)
PA5: CN5.2 J4.2 U1.18(PA5)
PA6: C23.2 R54.1 TP8.1 U1.19(PA6)
PA7: R42.1 R45.2 R48.2 TP5.1 U1.20(PA7)
PA8: CN9.8 U1.44(PA8)
PA9: CN9.2 R111.1 U1.45(PA9)
PA10: CN9.1 R109.1 U1.46(PA10)
PA11: CN9.7 U1.47(PA11) U2.4(RXD)
PA12: CN9.6 U1.48(PA12) U2.1(TXD)
PA13: J3.2 R113.1 U1.49(PA13)
PA14: J3.4 R112.1 U1.50(PA14)
PA15: CN5.10 J3.8 U1.51(PA15)
PB0: R43.1 R46.2 R49.2 TP6.1 U1.23(PB0)
PB1: C24.2 R55.1 TP9.1 U1.24(PB1)
PB2: C24.1 R52.2 R55.2 R75.2 U1.25(PB2)
PB3: CN5.6 J3.6 R115.1 U1.54(PB3)
PB4: CN5.5 U1.55(PB4)
PB5: CN5.4 U1.56(PB5)
PB6: C34.1 D12.2(A) R81.2 R85.2 U1.57(PB6)
PB7: C35.1 D13.2(A) R82.2 R86.2 U1.58(PB7)
PB8: C36.1 D14.2(A) R83.2 R88.2 U1.59(PB8)
PB9: CN5.9 U1.60(PB9)
PB10: CN9.4 R96.2 U1.28(PB10)
PC0: C25.2 D9.2(A) R57.2 R62.2 R70.2 U1.9(PC0)
PC1: C26.2 D10.2(A) R59.2 R63.2 R71.2 U1.10(PC1)
PC2: C27.2 D11.2(A) R61.2 R64.2 R72.2 U1.11(PC2)
PC3: R38.1 R67.2 U1.12(PC3)
PC4: C20.2 NTC1.2 R40.2 U1.21(PC4)
PC5: C23.1 R51.2 R54.2 R74.2 U1.22(PC5)
PC13: R91.2 U1.3(PC13)
PC14: CN9.3 R99.2 U1.4(PC14) U2.5(SHDN)
PC15: CN9.5 U1.5(PC15)
PD2: CN5.1 U1.53(PD2)
PF0: C4.1 R68.2 U1.6(PF0) X1.1
PF1: C5.2 R69.2 U1.7(PF1) X1.3
PG10: CN6.3 J3.10 R92.2 R118.1 U1.8(PG10)
SCREF: C3.2 J2.2 R2.1 R3.2 U1.52(SCREF)
STLINK_LED: R121.1 R122.1 U5.30(PA9)
STLINK_NRST: R118.2 U5.18(PB0)
STLINK_SWCLK: R112.2 U5.26(PB13)
STLINK_SWDIO: R113.2 R114.2 U5.25(PB12)
STLINK_SWO: R115.2 U5.31(PA10)
STLINK_UART_RX: R111.2 U5.13(PA3)
STLINK_UART_TX: R109.2 U5.12(PA2)
SW: D1.1 L1.1 U1.62(SW)
U: CON1.1 CON1.2 Q1.1(S) Q1.2(S) Q1.3(S) Q4.5(D) Q4.6(D) Q4.7(D) Q4.8(D) R16.1 R19.2 R56.1
USB_DM: U4.6(I/O1#6) U5.32(PA11)
USB_DP: R104.1 U4.4(I/O2#4) U5.33(PA12)
USB_RENUM: R102.2 U5.38(PA15)
V: CON1.3 CON1.4 Q2.1(S) Q2.2(S) Q2.3(S) Q5.5(D) Q5.6(D) Q5.7(D) Q5.8(D) R17.1 R20.2 R58.1
VHALL: C37.2 J6.4 R84.1 R87.1 R89.1
VM: C13.2 C14.2 C15.2 C31.1 C32.1 C33.1 CON2.1 CON2.2 Q1.5(D) Q1.6(D) Q1.7(D) Q1.8(D) Q2.5(D) Q2.6(D) Q2.7(D) Q2.8(D) Q3.5(D) Q3.6(D) Q3.7(D) Q3.8(D) R1.1 R37.2 R76.1
VREF+: C10.2 C11.1 C30.1 CN5.8 J5.6 NTC1.1 R9.1 R41.2 R42.2 R43.2 TR1.1 U1.26(VREFP)
VREGIN: J5.2 R6.1 R66.1 U1.64(REGIN)
VSHUNT1N: NET1.1 R50.1
VSHUNT1P: JP1.1 Q4.1(S) Q4.2(S) Q4.3(S) R28.1 R31.2 R32.2 R44.1
VSHUNT2N: NET2.1 R51.1
VSHUNT2P: JP1.2 JP2.1 Q5.1(S) Q5.2(S) Q5.3(S) R29.1 R33.2 R34.2 R45.1
VSHUNT3N: NET3.1 R52.1
VSHUNT3P: JP2.2 Q6.1(S) Q6.2(S) Q6.3(S) R30.1 R35.2 R36.2 R46.1
W: CON1.5 CON1.6 Q3.1(S) Q3.2(S) Q3.3(S) Q6.5(D) Q6.6(D) Q6.7(D) Q6.8(D) R18.1 R21.2 R60.1
N170257: D5.2(A) R22.1
N170269: Q4.4(G) R22.2 R25.2 R28.2
N170415: Q1.4(G) R10.2 R13.2 R16.2
N170423: D2.2(A) R10.1
N174120: Q5.4(G) R23.2 R26.2 R29.2
N174124: D6.2(A) R23.1
N174270: Q2.4(G) R11.2 R14.2 R17.2
N174282: D3.2(A) R11.1
N174784: Q6.4(G) R24.2 R27.2 R30.2
N174788: D7.2(A) R24.1
N174934: Q3.4(G) R12.2 R15.2 R18.2
N174946: D4.2(A) R12.1
N180167: R116.1 U5.2(PC13-TAMPER-RTC)
N180187: R117.1 U5.3(PC14-OSC32_IN)
N180745: R105.1 R106.2 U5.10(PA0-WKUP)
N180799: R114.1 U5.27(PB14)
N180929: J8.3 U4.3(I/O2#3)
N180941: J8.2 U4.1(I/O1#1)
N181071: Q7.2(E) R104.2
N181167: Q7.1(B) R101.1 R102.1 R103.2
N181233: R107.2 R110.1 U5.39(PB3/JTDO)
N181269: C47.2 U3.4(BYPASS)
N181591: LED4.K2 R121.2
N181595: LED4.A1 R122.2
N181645: C48.1 U5.5(OSCIN/PD0) X2.1
N181657: C49.1 U5.6(OSCOUT/PD1) X2.2
N181761: R119.2 U5.44(BOOT0)
N258505: J6.1 R78.2 R81.1
N258509: J6.2 R79.2 R82.1
N258513: J6.3 R80.2 R83.1
N261648: C40.1 R90.1 R92.1 SW3.1 SW3.2
N262399: C39.1 R95.1 R96.1 R97.1 SW2.1 SW2.2
N265543: R76.2 R77.1
N265547: LED1.2 R77.2
N274832: CN6.2 R65.1
N274924: CN6.8 R66.2
N274964: CN8.4 R70.1 R73.1
N274968: CN8.5 R71.1 R74.1
N274972: CN8.6 R72.1 R75.1
N520147: LED3.2 R95.2
N538821: CN8.1 R67.1
N539050: CN8.3 R69.1
N539062: CN8.2 R68.1
N683197: C38.1 R91.1 R93.1 R94.1 SW1.1 SW1.2
N683205: LED2.2 R94.2
N684002: C21.2 R38.2 TP3.1 TR1.2
N685395: J7.1 R98.2 U2.7(CANH)
N685399: J7.2 R98.1 U2.6(CANL)
N685471: J7.4 R100.2
N728166: R58.2 R59.1
N728550: R60.2 R61.1
N729020: R56.2 R57.1
N741558: R105.2 R108.2
N741774: C2.2 R1.2 U1.61(VM)

Not connected (* = marked no-connect by the designer): CN6 1*; J3 7*; J8 4*; J9 6* 7* 8*; U5 4(PC15-OSC32_OUT)* 11(PA1)* 14(PA4)* 15(PA5)* 16(PA6)* 17(PA7)* 19(PB1)* 21(PB10)* 22(PB11)* 28(PB15)* 29(PA8)* 40(PB4/JNTRST)* 41(PB5)* 42(PB6)* 43(PB7)* 45(PB8)* 46(PB9)*

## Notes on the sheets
sheet 1
- SWCLK/JTCK
- SWDIO/JTMS
- SWO/JTDO
- DIS
- HALL3
- HALL2
- HALL1
- JTDI
- VDSMON
- Open (deafult): SC
  protection enabled
- Closed: SC
  protection disabled
- CAN TX
- CAN RX
- USER1
- UART RX
- CAN_SHDN
- UART TX
- OSC_OUT
- OSC_IN
- nRST
- VOUT1
- VOUT2
- VOUT3
- OPP1
- VBUS
- OPO1
- OPN1
- USER2
- DAC1
- DAC2
- OPO2
- OPP2
- NTC
- OPN2
- OPP3
- OPO3
- OPN3
- GND
sheet 2
- GND
sheet 3
- Current sensing circuitry topology
- 2 OpAmp
  (OP1 + OP2)
- 3 OpAmp
- PGA
- IN1+
- PA1
- PA1
- PA1
- SPEED
- IN1-
- PA3
- VBUS monitoring
- Debug outputs
- OUT1
- PA2
- PA2
- COMP3
- DAC1
- IN2+
- PA7
- PA7
- PA7
- DAC2
- IN2-
- PC5
- GND
- OUT2
- PA6
- PA6
- IN3+
- PB0
- PB0
- PB0
- IN3-
- PB2
- OUT3
- PB1
- OPP1
- OPP2
- OPP3
- +
- +
- +
- COMP1
- COMP2
- COMP4
- OPO1
- OPO2
- OPO3
- OP1
- OP2
- OP3
- -
- -
- -
- GND
- GND
sheet 4
- D15
- I2C1_SCL
- NC
- D14
- I2C1_SDA
- IOREF
- NRST
- AREF
- GND
- 3.3V
- SWO
- D13
- SPI1_SCK
- 5V
- D12
- SPI1_MISO
- GND
- D11
- SPI1_MOSI
- TIM17_CH1
- GND
- D10
- SPI1_NSS
- TIM3_CH2
- VIN
- D9
- TIM2_CH1
- D8
- D7
- CANBus
- D6
- TIM4_CH1
- A0
- A1
- CANBus
- D4
- D5
- TIM4_CH2
- A2
- USER2
- D3
- TIM2_CH3
- A3
- CANBus
- D2
- A4
- SPEED
- VirtualCOM
- D1
- UART1_TX
- A5
- VirtualCOM
- D0
- UART1_RX
- OSC_IN
- OSC_OUT
- VOUT1
- VOUT2
- VOUT3
- OPN1
- OPN2
- OPN3
sheet 5
- U
- VM
- V
- GND
- VCC
- VREGIN
- VDD
- VBAT
- VDDA
- VREF+
- GND
- W
- H1
- H2
- H3
- VHALL
- GND
- USER1/WAKE
- USER2
- RESET
- CANH
- CANL
- GND
- SHIELD
sheet 6
- VCC
- D-
- D+
- ID
- GND
- SWDIO
